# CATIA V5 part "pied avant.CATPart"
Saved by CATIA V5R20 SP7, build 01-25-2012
Part number: pied avant bati
Bounding box of the stored display mesh (mm): x -29.09 to -10.49, y -86 to -58, z -35 to 75
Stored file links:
  F:\Travaux\Modélisations\CFAO_2011\CFAO_2011_MMS\CFAO_2011_MMS_DONE\CFAO_2011_MMS_jboiteux\Catia\pied avant.CATPart
  U:\finthinkmotion\stepper.CATProduct
  F:\Travaux\Modélisations\CFAO_2011\CFAO_2011_MMS\CFAO_2011_MMS_DONE\CFAO_2011_MMS_jboiteux\Catia\Part1.CATPart
  F:\Travaux\Modélisations\CFAO_2011\CFAO_2011_MMS\CFAO_2011_MMS_DONE\CFAO_2011_MMS_jboiteux\Catia\bati.CATPart
  F:\Travaux\Modélisations\CFAO_2011\CFAO_2011_MMS\CFAO_2011_MMS_DONE\CFAO_2011_MMS_jboiteux\Catia\Part2.CATPart
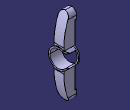
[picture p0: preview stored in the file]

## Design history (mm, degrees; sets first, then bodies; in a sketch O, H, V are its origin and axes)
Parameters
  rayontube = 9 mm {= External.royontubebati}
External parameters (linked from other documents)
  External.royontubebati = 9 mm
Set1
  Plane1: linked copy from another document
  DatumCurve1: linked copy from another document
  Point1: linked copy from another document
  DatumSurface1: linked copy from another document
  DatumSurface2: linked copy from another document
  Line1 to Line3: linked copy from another document
  DatumSurface3: linked copy from another document
  Plane2: linked copy from another document
  Line4: linked copy from another document
  Plane3: linked copy from another document
Body1 (main body)
  Sketch1 on Plane1, origin (-26.69, 0, 0), H (0, 1, 0), V (0, 0, 1)
    projected circle E1 centre (-72, 20) radius 12 from edge of DatumCurve1
    circle A1 centre (-72, 20) radius 14
    point P1 (-72, 20)
    point P2 (-120.5166, 0)
    reference projected point E2 (-72, 20) from Point1
    radius A1 = 14 {= rayontube *4/3+2mm}
    coincidence: E2 P1
  Pad1: profile Sketch1, direction (1, 0, 0), up to face of DatumSurface1
  Sketch2 on end face of Pad1, origin (-24.89, 0, 0), H (0, 1, 0), V (0, 0, 1)
    projected circle E1 centre (-72, 20) radius 14 from edge [end face of Pad1 | face of Pad1 from Sketch1.A1]
    projected arc E2 centre (-72, 20) radius 14 from (-61.2762, 29) to (-61.2762, 11) ccw from edge [end face of Pad1 | face of Pad1 from Sketch1.A1]
    projected circle E3 centre (-72, 20) radius 12 from edge [face of Pad1 from Sketch1.E1 | end face of Pad1]
    projected arc E4 centre (-72, 20) radius 12 from (-79.9373, 29) to (-79.9373, 11) ccw from edge [face of Pad1 from Sketch1.E1 | end face of Pad1]
    line L1 (-79.9373, 11) -> (-61.2762, 11)
    point P1 (-79.9373, 11)
    point P2 (-61.2762, 11)
    line L2 (-79.9373, 29) -> (-61.2762, 29)
    point P3 (-79.9373, 29)
    point P4 (-61.2762, 29)
    distance L2 L1 = 18 {= rayontube *2}
    distance P1 P3 = 18 {= rayontube *2}
    coincidence: P1 E3, P2 E1, P3 E3, P4 E1
    horizontal: L1 H, L2 H
  Pad2: profile Sketch2, direction (1, 0, 0), up to face of DatumSurface2
  Plane4: type 2Lines, Element1 edge [face of Pad2 from Sketch2.L1 | face of Pad1], Element2 edge [face of Pad1 | face of Pad2 from Sketch2.L2]
  Point2: type OnCurve, Support Line3, Length 12 {= rayontube *4/3}
  Line5: type Normal, RefPoint Point2, RefSkin DatumSurface3, Start 0, End 20
  Plane5: type Angle, RefPlane Plane4, Direction Line5, Angle -38
  Split1: SplitPlane Plane5
  Plane6: type OffsetPt, RefPlane Plane2, RefPoint Point1
  Sketch3 on Plane6, origin (0, -72, 0), H (1, 0, 0), V (0, 0, 1)
    point P1 (-26.69, 36)
    line L1 (-26.69, 36) -> (-26.69, 63)
    point P2 (-26.69, 63)
    line L2 (-26.69, 63) -> (-29.09, 63)
    point P3 (-29.09, 63)
    line L3 (-29.09, 63) -> (-29.09, 75)
    point P4 (-29.09, 75)
    line L4 (-29.09, 75) -> (-20.09, 75)
    point P5 (-20.09, 75)
    line L5 (-26.69, 36) -> (-11.49, 36)
    point P6 (-11.49, 36)
    spline S1 through (-20.09, 75) (-12.69, 52.4) (-11.49, 36)
    reference projected line E1 (-26.69, 40) -> (-26.69, 0) from Line2
    reference projected line E2 (-29.69, 20) -> (-17.69, 20) from Line4
    reference projected line E3 (-17.69, 20) -> (62.31, 20) from Line1
    reference projected line E4 through (0, 20) direction (1, 0) from axis of face of Pad1
    spline S2 through (-20.09, -35) (-12.69, -12.4) (-11.49, 4)
    point P9 (-20.09, -35)
    point P10 (-29.09, -35)
    line L6 (-29.09, -35) -> (-20.09, -35)
    reference projected line E5 through (0, 20) direction (1, 0) from axis of face of Pad1
    point P13 (-29.09, -35)
    point P14 (-29.09, -23)
    line L7 (-29.09, -23) -> (-29.09, -35)
    reference projected line E6 through (0, 20) direction (1, 0) from axis of face of Pad1
    point P17 (-29.09, -23)
    point P18 (-26.69, -23)
    line L8 (-26.69, -23) -> (-29.09, -23)
    reference projected line E7 through (0, 20) direction (1, 0) from axis of face of Pad1
    point P21 (-26.69, -23)
    point P22 (-26.69, 4)
    line L9 (-26.69, 4) -> (-26.69, -23)
    point P23 (-11.49, 4)
    point P24 (-26.69, 4)
    line L10 (-26.69, 4) -> (-11.49, 4)
    reference projected line E8 (-10.49, 34) -> (-10.49, 6) from edge [face of Pad1 | end face of Pad2]
    point P25 (-20.09, 75)
    point P26 (-11.49, 36)
    point P27 (-12.69, 52.4)
    point P28 (-11.49, 4)
    point P29 (-20.09, -35)
    point P30 (-12.69, -12.4)
    length L3 = 12 {= rayontube *4/3}
    length L2 = 2.4 {= rayontube *4/15}
    angle L2 L3 = 90
    length L4 = 9 {= rayontube}
    length L1 = 27 {= rayontube *3}
    distance E1 L1 = 0
    distance E2 L5 = 16 {= rayontube*4/3+4mm}
    distance P27 E3 = 32.4 {= rayontube *3.6}
    distance E8 P26 = 1
    distance P27 L1 = 14 {= rayontube +5mm}
    vertical: L1 V, L3 V
    horizontal: L4 H, L5 H
    coincidence: P25 P5, P26 P6, P29 P9, P28 P23, P10 P13, P14 P17, P18 P21, P22 P24
    symmetry: S1 S2 E4, P26 P28 E4, P25 P29 E4, P27 P30 E4, P5 P9 E4, P4 P10 E4, L4 L6 E4, P4 P13 E5, P3 P14 E5, L3 L7 E5, P3 P17 E6, P2 P18 E6, L2 L8 E6, P2 P21 E7, P1 P22 E7, L1 L9 E7, P6 P23 E7, P1 P24 E7, L5 L10 E7
  Pad3: profile Sketch3, direction (0, -1, 0), length 7 {= rayontube /9*7}, mirrored extent
  Sketch4 on face of Pad3 from Sketch3.L5, origin (0, 0, 36), H (1, 0, 0), V (0, -1, 0)
  Sketch5 on face of Pad3 from Sketch3.L10, origin (0, 0, 4), H (1, 0, 0), V (0, 1, 0)
  Pad4: profile Sketch4, direction (0, 0, -1), up to Plane3
  Pad5: profile Sketch5, direction (0, 0, 1), up to Plane3
  Sketch6 on Plane1, origin (-26.69, 0, 0), H (0, 1, 0), V (0, 0, 1)
    circle A1 centre (-72, 20) radius 12
    point P1 (-72, 20)
    reference projected point E1 (-72, 20) from Point1
    radius A1 = 12 {= rayontube *4/3}
    coincidence: E1 P1
  Pocket1: profile Sketch6, direction (-1, 0, 0), up to end face of Pad2
  Fillet1: radius 7 {= rayontube *7/9}, on edge [face of Pad3 from Sketch3.L6 | face of Pad3]; edge [face of Pad3 | face of Pad3 from Sketch3.L6]
  Fillet2: radius 7 {= rayontube *7/9}, on edge [face of Pad3 from Sketch3.L4 | face of Pad3]; edge [face of Pad3 | face of Pad3 from Sketch3.L4]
